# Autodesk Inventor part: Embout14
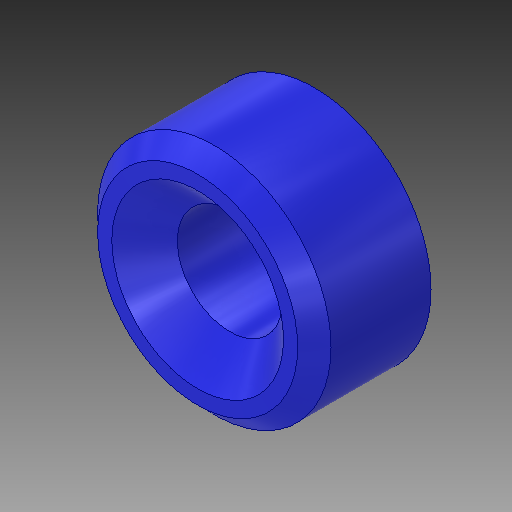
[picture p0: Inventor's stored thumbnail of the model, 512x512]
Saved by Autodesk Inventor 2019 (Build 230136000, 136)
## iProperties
Created: 2000-02
Part Number: Embout14
Material: Générique
Document SubType Name: Modeling
Designer: si-nd67
Density: 1 g/cm^3
Appearance: Bleu - Peinture murale - Brillant
Mass: 0.792099 g
Surface Area: 6.47007 cm^2
Volume: 0.792099 cm^3
Sending System: SolidWorks 2014
Last Author: tjost
Last Saved: 2019-02-07
Author: si-nd67
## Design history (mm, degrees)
feature "Perçage2"
node "Solide1"
